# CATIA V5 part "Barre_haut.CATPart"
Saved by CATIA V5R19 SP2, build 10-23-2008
Part number: Barre_haut
Bounding box of the stored display mesh (mm): x -16.329 to 16.329, y -779.922 to -284.079, z 70.079 to 149.921
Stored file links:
  G:\EU_thinkMotion\CFAO_2010\MMS_groupe3\MMS_groupe3\pmayet\pmayet_assemblage_animation\pmayet_assemblage_animation\Barre_haut.CATPart
  G:\EU_thinkMotion\CFAO_2010\MMS_groupe3\MMS_groupe3\pmayet\pmayet_assemblage_animation\pmayet_assemblage_animation\pmayet_assemblage_animation.CATProduct
  G:\EU_thinkMotion\CFAO_2010\MMS_groupe3\MMS_groupe3\pmayet\pmayet_assemblage_animation\pmayet_assemblage_animation\Squelette_barre_haut.CATPart
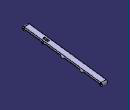
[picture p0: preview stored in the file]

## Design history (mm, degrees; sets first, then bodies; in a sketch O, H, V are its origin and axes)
Parameters
  Rayon_trou = 5 mm
  Rayon_porte_moyeu = 96 mm
  Distance_entre_rayons(porte_moyeu) = 32 mm
  Rayon_trou_amortisseur = 5 mm
  `Longueur=Angle_Patte_haut(porte_moyeu)` = 10
  Epaisseur_amortisseur = 6 mm
Set1
  Plane1: linked copy from another document
  Line1: linked copy from another document
  Plane2: linked copy from another document
  Plane3: linked copy from another document
  Point1: linked copy from another document
  Point2: linked copy from another document
  Plane4: linked copy from another document
  Point3 to Point5: linked copy from another document
  Point6 "Point.19_amortisseur": linked copy from another document
Body1 (main body)
  Sketch1 on Plane1, origin (0, 0, 0), H (0, 1, 0), V (0, 0, 1)
    line L1 (-768.7494, 149.9215) -> (-292.7494, 89.9215)
    point P1 (-768.7494, 149.9215)
    point P2 (-292.7494, 89.9215)
    reference projected line E1 (-770, 140) -> (-294, 80) from Line1
    line L2 (-771.2506, 130.0785) -> (-295.2506, 70.0785)
    point P3 (-771.2506, 130.0785)
    point P4 (-295.2506, 70.0785)
    reference projected line E2 (-770, 140) -> (-294, 80) from Line1
    reference projected line E3 (-770, 140) -> (-294, 80) from Line1
    reference projected line E4 (-770, 140) -> (-294, 80) from Line1
    reference intersected line E5 through (-299.3281, 37.7304) direction (0.1251, 0.9921) from Plane2
    reference intersected line E6 through (-299.3281, 37.7304) direction (0.1251, 0.9921) from Plane2
    reference intersected line E7 through (-775.3281, 97.7304) direction (0.1251, 0.9921) from Plane3
    reference intersected line E8 through (-775.3281, 97.7304) direction (0.1251, 0.9921) from Plane3
    arc A1 centre (-294, 80) radius 10 from (-295.2506, 70.0785) to (-292.7494, 89.9215) ccw
    point P5 (-294, 80)
    point P6 (-295.2506, 70.0785)
    point P7 (-292.7494, 89.9215)
    reference projected point E9 (-294, 80) from Point1
    arc A2 centre (-770, 140) radius 10 from (-768.7494, 149.9215) to (-771.2506, 130.0785) ccw
    point P8 (-770, 140)
    point P9 (-768.7494, 149.9215)
    point P10 (-771.2506, 130.0785)
    reference projected point E10 (-770, 140) from Point2
    distance E3 L1 = 10 {= Rayon_trou * 2}
    distance E4 L2 = 10 {= Rayon_trou * 2}
    distance E5 P4 = 0
    distance E6 P2 = 0
    distance E7 P3 = 0
    distance E8 P1 = 0
    radius A1 = 10 {= Rayon_trou *2}
    distance P6 P4 = 0
    distance P2 P7 = 0
    radius A2 = 10 {= Rayon_trou *2}
    distance P1 P9 = 0
    distance P10 P3 = 0
    parallelism: L1 E1, L2 E2
    coincidence: P5 E9, P8 E10
  Pad1: profile Sketch1, direction (1, 0, 0), length 8.3289 {= (Rayon_porte_moyeu + Distance_entre_rayons(porte_moyeu) )*`Longueur=Angle_Patte_haut(porte_moyeu)` *3.14/180 - 14mm}, mirrored extent
  Sketch2 on Plane1, origin (0, 0, 0), H (0, 1, 0), V (0, 0, 1)
    line L1 (-768.7494, 149.9215) -> (-292.7494, 89.9215)
    point P1 (-768.7494, 149.9215)
    point P2 (-292.7494, 89.9215)
    line L2 (-760.0785, 138.7494) -> (-660.9215, 126.2506)
    point P3 (-760.0785, 138.7494)
    point P4 (-660.9215, 126.2506)
    reference projected line E1 (-770, 140) -> (-294, 80) from Line1
    reference projected line E2 (-770, 140) -> (-294, 80) from Line1
    reference projected line E3 (-770, 140) -> (-294, 80) from Line1
    reference intersected line E4 through (-775.3281, 97.7304) direction (0.1251, 0.9921) from Plane3
    reference intersected line E5 through (-299.3281, 37.7304) direction (0.1251, 0.9921) from Plane2
    reference projected line E6 (-770, 140) -> (-294, 80) from Line1
    arc A1 centre (-294, 80) radius 10 from (-303.9215, 81.2506) to (-292.7494, 89.9215) ccw
    point P5 (-294, 80)
    point P6 (-303.9215, 81.2506)
    point P7 (-292.7494, 89.9215)
    reference projected point E7 (-294, 80) from Point1
    reference intersected line E8 through (5.3281, 42.2696) direction (0.9921, -0.1251) from Plane4
    arc A2 centre (-413, 95) radius 10 from (-422.9215, 96.2506) to (-403.0785, 93.7494) ccw
    point P8 (-413, 95)
    point P9 (-422.9215, 96.2506)
    point P10 (-403.0785, 93.7494)
    reference projected point E9 (-413, 95) from Point3
    reference intersected line E10 through (5.3281, 42.2696) direction (0.9921, -0.1251) from Plane4
    reference intersected line E11 through (5.3281, 42.2696) direction (0.9921, -0.1251) from Plane4
    arc A3 centre (-532, 110) radius 10 from (-541.9215, 111.2506) to (-522.0785, 108.7494) ccw
    point P11 (-532, 110)
    point P12 (-541.9215, 111.2506)
    point P13 (-522.0785, 108.7494)
    reference projected point E12 (-532, 110) from Point4
    reference intersected line E13 through (5.3281, 42.2696) direction (0.9921, -0.1251) from Plane4
    reference intersected line E14 through (5.3281, 42.2696) direction (0.9921, -0.1251) from Plane4
    arc A4 centre (-651, 125) radius 10 from (-660.9215, 126.2506) to (-641.0785, 123.7494) ccw
    point P14 (-651, 125)
    point P15 (-660.9215, 126.2506)
    point P16 (-641.0785, 123.7494)
    reference intersected line E15 through (5.3281, 42.2696) direction (0.9921, -0.1251) from Plane4
    reference intersected line E16 through (5.3281, 42.2696) direction (0.9921, -0.1251) from Plane4
    arc A5 centre (-770, 140) radius 10 from (-768.7494, 149.9215) to (-760.0785, 138.7494) ccw
    point P17 (-770, 140)
    point P18 (-768.7494, 149.9215)
    point P19 (-760.0785, 138.7494)
    reference projected point E17 (-770, 140) from Point2
    reference intersected line E18 through (5.3281, 42.2696) direction (0.9921, -0.1251) from Plane4
    line L3 (-641.0785, 123.7494) -> (-541.9215, 111.2506)
    point P20 (-641.0785, 123.7494)
    point P21 (-541.9215, 111.2506)
    reference projected line E19 (-770, 140) -> (-294, 80) from Line1
    reference projected line E20 (-770, 140) -> (-294, 80) from Line1
    line L4 (-522.0785, 108.7494) -> (-422.9215, 96.2506)
    point P22 (-522.0785, 108.7494)
    point P23 (-422.9215, 96.2506)
    line L5 (-403.0785, 93.7494) -> (-303.9215, 81.2506)
    point P24 (-403.0785, 93.7494)
    point P25 (-303.9215, 81.2506)
    reference projected line E21 (-770, 140) -> (-294, 80) from Line1
    reference projected line E22 (-770, 140) -> (-294, 80) from Line1
    reference projected line E23 (-770, 140) -> (-294, 80) from Line1
    reference projected line E24 (-770, 140) -> (-294, 80) from Line1
    reference projected point E25 (-651, 125) from Point6
    distance E3 L1 = 10 {= Rayon_trou * 2}
    distance P1 E4 = 0
    distance E5 P2 = 0
    distance E6 L2 = 0
    radius A1 = 10 {= Rayon_trou *2}
    distance P2 P7 = 0
    distance P6 E8 = 0
    radius A2 = 10 {= Rayon_trou *2}
    distance E10 P9 = 0
    distance P10 E11 = 0
    radius A3 = 10 {= Rayon_trou *2}
    distance E13 P12 = 0
    distance E14 P13 = 0
    radius A4 = 10 {= Rayon_trou_amortisseur *2}
    distance E15 P15 = 0
    distance P16 E16 = 0
    radius A5 = 10 {= Rayon_trou *2}
    distance P1 P18 = 0
    distance P19 E18 = 0
    distance P19 P3 = 0
    distance P15 P4 = 0
    distance E20 L3 = 0
    distance P16 P20 = 0
    distance P21 P12 = 0
    distance E23 L4 = 0
    distance E24 L5 = 0
    distance P13 P22 = 0
    distance P9 P23 = 0
    distance P10 P24 = 0
    distance P6 P25 = 0
    parallelism: L2 E1, E2 L1, L3 E19, E21 L4, L5 E22
    coincidence: E7 P5, E9 P8, P11 E12, P17 E17, P14 E25
  Pad2: profile Sketch2, direction (1, 0, 0), length 16.3289 {= (Rayon_porte_moyeu + Distance_entre_rayons(porte_moyeu) )*`Longueur=Angle_Patte_haut(porte_moyeu)` *3.14/180 - 6mm}, mirrored extent
  Sketch3 on Plane1, origin (0, 0, 0), H (0, 1, 0), V (0, 0, 1)
    circle A1 centre (-770, 140) radius 5
    point P1 (-770, 140)
    reference projected point E1 (-770, 140) from Point2
    distance P1 A1 = 5 {= Rayon_trou}
    coincidence: P1 E1
  Pocket1: profile Sketch3, direction (-1, 0, 0), length 16.3289 {= (Rayon_porte_moyeu + Distance_entre_rayons(porte_moyeu) )*`Longueur=Angle_Patte_haut(porte_moyeu)` *3.14/180-6mm}, mirrored extent
  Sketch4 on Plane1, origin (0, 0, 0), H (0, 1, 0), V (0, 0, 1)
    circle A1 centre (-651, 125) radius 5
    point P1 (-651, 125)
    reference projected point E1 (-651, 125) from Point6
    distance A1 P1 = 5 {= Rayon_trou_amortisseur}
    coincidence: P1 E1
  Pocket2: profile Sketch4, direction (-1, 0, 0), length 16.3289 {= (Rayon_porte_moyeu +Distance_entre_rayons(porte_moyeu) )*`Longueur=Angle_Patte_haut(porte_moyeu)` * 3.14/180 -6mm}, mirrored extent
  Sketch5 on Plane1, origin (0, 0, 0), H (0, 1, 0), V (0, 0, 1)
    circle A1 centre (-294, 80) radius 5
    point P1 (-294, 80)
    reference projected point E1 (-294, 80) from Point1
    distance P1 A1 = 5 {= Rayon_trou}
    coincidence: P1 E1
  Pocket3: profile Sketch5, direction (-1, 0, 0), length 16.3289 {= (Rayon_porte_moyeu + Distance_entre_rayons(porte_moyeu) )*`Longueur=Angle_Patte_haut(porte_moyeu)` *3.14/180- 6mm}, mirrored extent
  Sketch6 on Plane1, origin (0, 0, 0), H (0, 1, 0), V (0, 0, 1)
    arc A1 centre (-651, 125) radius 15 from (-665.8822, 126.8759) to (-636.1178, 123.1241) ccw
    point P1 (-651, 125)
    point P2 (-665.8822, 126.8759)
    point P3 (-636.1178, 123.1241)
    reference projected line E1 (-770, 140) -> (-294, 80) from Line1
    reference projected line E2 (-770, 140) -> (-294, 80) from Line1
    line L1 (-664.6316, 136.7974) -> (-634.8672, 133.0456)
    line L2 (-634.8672, 133.0456) -> (-636.1178, 123.1241)
    line L3 (-665.8822, 126.8759) -> (-664.6316, 136.7974)
    point P6 (-636.1178, 123.1241)
    point P7 (-665.8822, 126.8759)
    reference projected line E3 (-768.7494, 149.9215) -> (-292.7494, 89.9215) from edge [end face of Pad2 | face of Pad2 from Sketch2.L1]
    reference projected line E4 (-768.7494, 149.9215) -> (-292.7494, 89.9215) from edge [end face of Pad2 | face of Pad2 from Sketch2.L1]
    reference projected point E5 (-651, 125) from Point6
    reference projected point E6 (-651, 125) from Point6
    reference projected point E7 (-651, 125) from Point6
    radius A1 = 15 {= Rayon_trou_amortisseur *3}
    distance P2 E1 = 0
    distance E2 P3 = 0
    distance L1 E3 = 0
    distance P6 P3 = 0
    distance P7 P2 = 0
    distance E6 L3 = 15 {= 3 * Rayon_trou_amortisseur}
    distance E7 L2 = 15 {= Rayon_trou_amortisseur * 3}
    parallelism: L2 L3, L1 E4
    perpendicularity: L1 L3
    coincidence: P1 E5
  Pocket4: profile Sketch6, direction (-1, 0, 0), length 6 {= Epaisseur_amortisseur}, mirrored extent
